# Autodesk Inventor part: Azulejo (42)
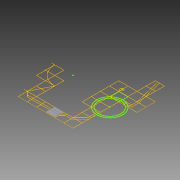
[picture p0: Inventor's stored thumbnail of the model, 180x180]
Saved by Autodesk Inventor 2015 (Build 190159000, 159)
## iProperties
Created: 2015-04
Part Number: Azulejo (42)
Material: Genérico
Document SubType Name: Modeling
Designer: Felipe
Density: 1 g/cm^3
Appearance: Padrão
Author: Felipe
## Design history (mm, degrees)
sketch "Sketch1"
  geometry: L1 (-1510, -7490)-(-1510, -6010); L2 (-3010, -1490)-(-3010, -10); L3 (-2990, 10)-(-1510, 10); L4 (-1510, -10)-(-2990, -10); L5 (-1510, -1490)-(-1510, -10); L6 (-1490, -10)-(-1490, -1490); L7 (-1490, -1490)-(-10, -1490); L8 (-10, -1510)-(-1490, -1510); L9 (-10, -2990)-(-10, -1510); L10 (-10, -5990)-(-10, -4510); L11 (-1490, -7490)-(-10, -7490); L12 (4490, -6010)-(3010, -6010); L13 (10, -1510)-(10, -2990); L14 (10, -3010)-(10, -4490); L15 (10, -4510)-(10, -5990); L16 (10, -5990)-(1490, -5990); L17 (1490, -6010)-(10, -6010); L18 (10, -7490)-(1490, -7490); L19 (1510, -5990)-(2990, -5990); L20 (2990, -6010)-(1510, -6010); L21 (1510, -7490)-(2990, -7490); L22 (4490, 1510)-(4490, 2990); L23 (4490, 10)-(4490, 1490); L24 (4490, -1490)-(4490, -10); L25 (4490, -2990)-(4490, -1510); L26 (3010, -5990)-(4490, -5990); L27 (3010, -7490)-(4490, -7490); L28 (4510, 3010)-(5990, 3010); L29 (5990, 2990)-(4510, 2990); L30 (4510, 2990)-(4510, 1510); L31 (4510, 1510)-(5990, 1510); L32 (5990, 1510)-(5990, 1740.185); L33 (5990, 1760.2)-(5990, 2259.8); L34 (5990, 2279.815)-(5990, 2990); L35 (5990, 1490)-(4510, 1490); L36 (4510, 1490)-(4510, 10); L37 (4510, 10)-(5990, 10); L38 (5990, 10)-(5990, 1490); L39 (5975.983, -10)-(4510, -10); L40 (4510, -10)-(4510, -1490); L41 (5990, -1510)-(5782.897, -1510); L42 (5782.897, -1510)-(5688.66, -1510); L43 (5668.66, -1510)-(5482.895, -1510); L44 (5482.895, -1510)-(5388.656, -1510); L45 (5368.656, -1510)-(4510, -1510); L46 (4510, -1510)-(4510, -2990); L47 (4510, -2990)-(5975.983, -2990); L48 (5990, -2975.728)-(5990, -2837.377); L49 (5990, -2837.377)-(5990, -2536.247); L50 (5990, -2500.476)-(5990, -2317.632); L51 (5990, -2317.632)-(5990, -1510); L52 (5990, -3010)-(4510, -3010); L53 (5990, -4490)-(5990, -3010); L54 (4510, -5990)-(5990, -5990); L55 (5990, -5990)-(5990, -4510); L56 (4510, -7490)-(5990, -7490); L57 (5990, -7490)-(5990, -6310); L58 (5990, -6290)-(5990, -6010); L59 (7490, 4510)-(7490, 5990); L60 (6010, 3010)-(7490, 3010); L61 (7490, 3010)-(7490, 4490); L62 (7490, 2990)-(6010, 2990); L63 (6010, 2990)-(6010, 2279.815); L64 (6010, 2259.8)-(6010, 1760.2)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; A1 r 250 centre (6000, 2010) between (5990, 2259.8) and (5990, 1760.2); A2 r 250 centre (6000, 2010) between (6010, 1760.2) and (6010, 2259.8); A3 r 270 centre (6000, 2010) between (5990, 2279.815) and (5990, 1740.185); A4 r 270 centre (6000, 2010) between (6010, 1740.185) and (6010, 2279.815); A5 r 3010.017 centre (0, 0) between (-1490, -2615.358) and (-346.554, -2990); A6 r 2990.017 centre (0, 0) between (-1490, -2592.316) and (-10, -2990); A7 r 3010.017 centre (0, 0) between (-2603.863, -1510) and (-1510, -2603.863); A8 r 2990.017 centre (0, 0) between (-2580.717, -1510) and (-1510, -2580.717); A9 r 3010.017 centre (0, 0) between (-2990, -346.554) and (-2615.358, -1490); A10 r 2990.017 centre (0, 0) between (-2990, -10) and (-2592.316, -1490); A11 r 2131.367 centre (7500, -1500) between (7490, 631.344) and (6010, 24.017); A12 r 2131.367 centre (7500, -1500) between (5975.983, -10) and (5368.656, -1490); A13 r 2131.367 centre (7500, -1500) between (5368.656, -1510) and (5975.983, -2990); A14 r 2131.367 centre (7500, -1500) between (6010, -3024.017) and (7190, -3608.703); A15 r 1831.367 centre (7500, -1500) between (7490.321, 331.342) and (6463.753, 10); A16 r 1831.367 centre (7500, -1500) between (7489.976, 331.34) and (6010, -435.196); A17 r 1831.367 centre (7500, -1500) between (5990, -463.753) and (5668.66, -1490); A18 r 1831.367 centre (7500, -1500) between (5668.66, -1510) and (5990, -2536.247); A19 r 1831.367 centre (7500, -1500) between (6010, -2564.804) and (6435.196, -2990); A20 r 1831.367 centre (7500, -1500) between (6463.753, -3010) and (7490, -3331.34); A21 r 2111.367 centre (7500, -1500) between (7490.389, 611.346) and (6024.272, 10); A22 r 2111.367 centre (7500, -1500) between (5990, -24.272) and (5388.656, -1490); A23 r 2111.367 centre (7500, -1500) between (5388.656, -1510) and (5990, -2975.728); A24 r 2111.367 centre (7500, -1500) between (6024.272, -3010) and (7210, -3591.357); A25 r 1811.367 centre (7499.986, -1499.91) between (7490.524, 311.432) and (6499.51, 10.09); A26 r 1811.367 centre (7500, -1500) between (6469.975, -10) and (6010, -469.975); A27 r 1811.367 centre (7500, -1500) between (5990, -499.524) and (5688.66, -1490); A28 r 1811.367 centre (7500, -1500) between (5688.66, -1510) and (5990, -2500.476); A29 r 1811.367 centre (7500, -1500) between (6010, -2530.025) and (6469.975, -2990); A30 r 1811.367 centre (7500, -1500) between (6499.524, -3010) and (7490, -3311.34); A31 r 449.871 centre (7499.449, -4060.672) between (7510, -4510.419) and (7521.546, -4510); A32 r 2111.367 centre (7500, -1500) between (7490.019, 611.344) and (7490.389, 611.346); A33 r 1831.367 centre (7500, -1500) between (7489.976, 331.34) and (7490.321, 331.342); A34 r 1811.367 centre (7499.986, -1499.91) between (7489.986, 311.429) and (7490.524, 311.432); A35 r 2131.367 centre (7500, -1500) between (7510, -3631.344) and (7190, -3608.703); A36 r 2131.367 centre (7500, -1500) between (7210, -3611.546) and (7490, -3631.344); 12 further points
  constraints: 718 end point, 82 point on circle, 36 centre point, 14 point on line, 3 concentric, 2 parallel, 2 perpendicular, 1 collinear, 1 horizontal, 1 vertical, 1 other
extrude "Extrusion1" new body sketch "Sketch1" distance "d0" = 60; taper "d1" = 0 deg
extrude "Extrusion2" new body sketch "Sketch1" distance "d2" = 60; taper "d3" = 0 deg
extrude "Extrusion3" new body sketch "Sketch1" distance "d4" = 60; taper "d5" = 0 deg
body "Solid1"
body "Solid2"
body "Solid3"
